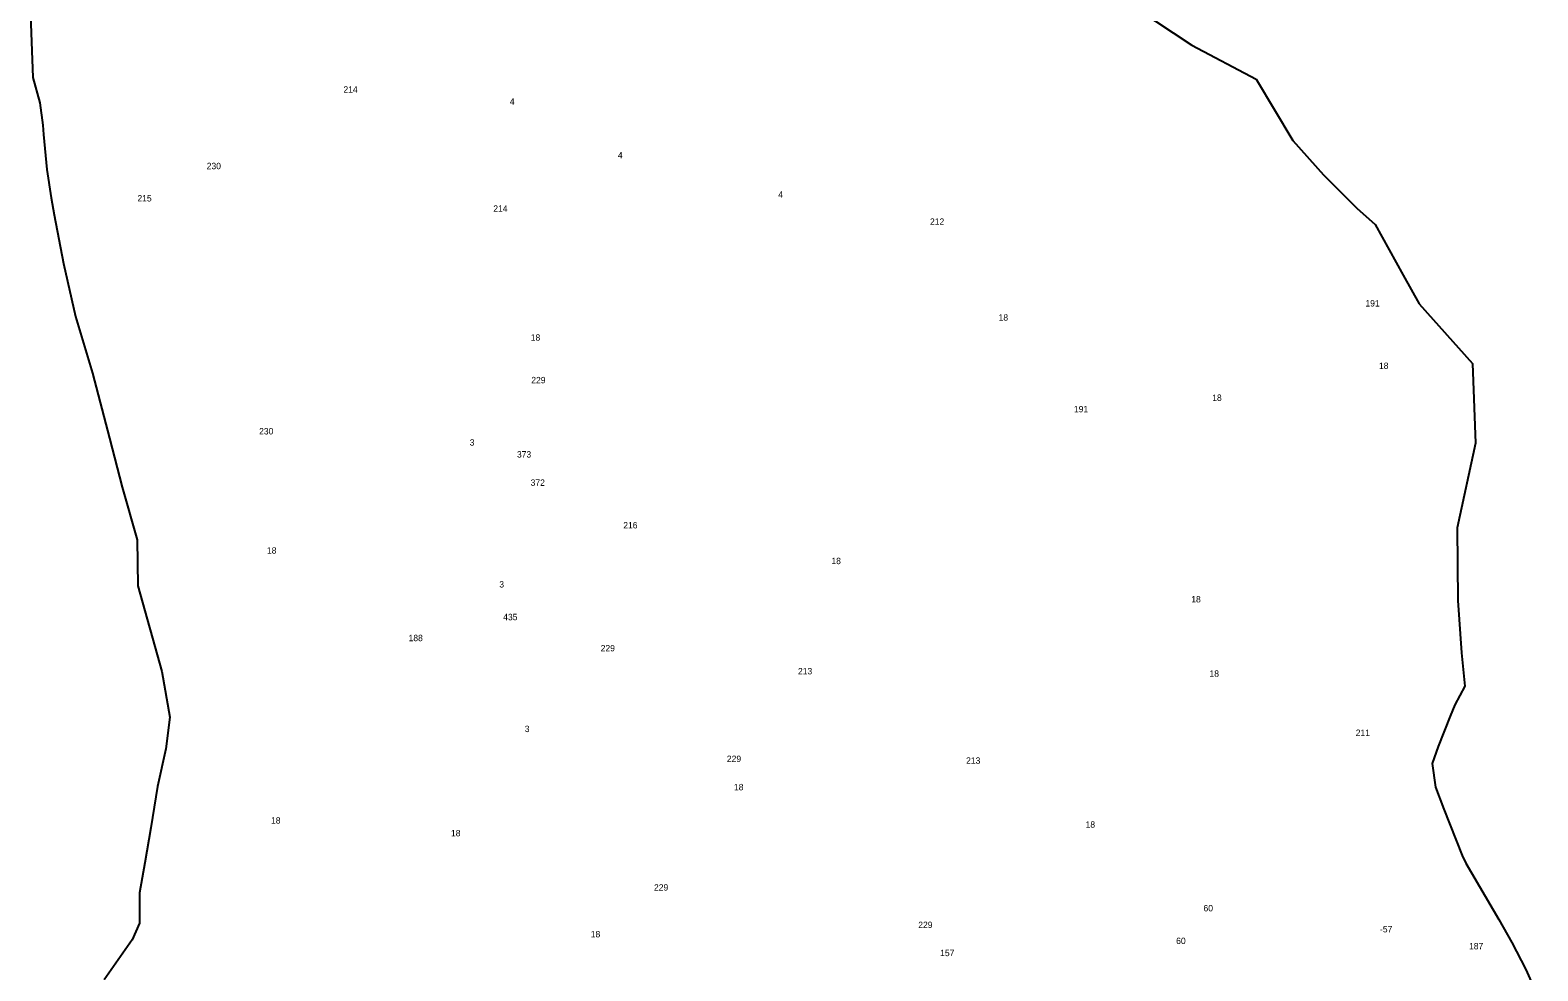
# Model space of a CAD drawing. Extents: x -784109 to -782312, y -974244 to -970866.
# Drawn here: x -784109 to -782747, y -972551 to -971701 of the extents above; entities that cross this region are included whole.
import ezdxf

# ---------------------------------------------------------------- set-up
doc = ezdxf.new("R2010")
doc.units = 0
doc.layers.add('Vrstva 13', color=7, linetype='Continuous')
doc.layers.add('Vrstva 24', color=7, linetype='Continuous')

msp = doc.modelspace()

# ---------------------------------------------------------------- linework, layer by layer
at = {"layer": 'Vrstva 13'}
for p, q in [((-784108.94, -971679.6), (-784106.6, -971743.94)), ((-783109.02, -971681.97), (-783059.31, -971714.69)), ((-783059.31, -971714.69), (-783001.1, -971745.38)), ((-784106.6, -971743.94), (-784100.18, -971766.7)), ((-783001.1, -971745.38), (-782968.1, -971800.86)), ((-784100.18, -971766.7), (-784097.5, -971786.9)), ((-784097.5, -971786.9), (-784096.81, -971795.31)), ((-784096.81, -971795.31), (-784094.01, -971827.06)), ((-782968.1, -971800.86), (-782940.26, -971831.9)), ((-784094.01, -971827.06), (-784089.81, -971852.51)), ((-782940.26, -971831.9), (-782910.24, -971862.08)), ((-784089.81, -971852.51), (-784087.24, -971868.04)), ((-782910.24, -971862.08), (-782893.59, -971876.77)), ((-784087.24, -971868.04), (-784078.84, -971911.94)), ((-782893.59, -971876.77), (-782868.37, -971922.43)), ((-784078.84, -971911.94), (-784068.07, -971959.81)), ((-782868.37, -971922.43), (-782853.98, -971948.24)), ((-782853.98, -971948.24), (-782805.79, -972002.19)), ((-784068.07, -971959.81), (-784052.69, -972010.82)), ((-784052.69, -972010.82), (-784037.23, -972069.65)), ((-782805.79, -972002.19), (-782803.02, -972074.24)), ((-784037.23, -972069.65), (-784025.79, -972114.01)), ((-782803.02, -972074.24), (-782819.67, -972150.58)), ((-784025.79, -972114.01), (-784012.26, -972161.41)), ((-784012.26, -972161.41), (-784011.59, -972202.98)), ((-782819.67, -972150.58), (-782819.09, -972216.09)), ((-784011.59, -972202.98), (-783989.83, -972280.32)), ((-782819.09, -972216.09), (-782815.75, -972263.49)), ((-782815.75, -972263.49), (-782812.71, -972293.53)), ((-783989.83, -972280.32), (-783982.66, -972321.69)), ((-782812.71, -972293.53), (-782821.58, -972310.58)), ((-782821.58, -972310.58), (-782826.05, -972320.69)), ((-783982.66, -972321.69), (-783986.26, -972350.29)), ((-782826.05, -972320.69), (-782836.83, -972348)), ((-783986.26, -972350.29), (-783993.77, -972384.26)), ((-782836.83, -972348), (-782842.07, -972363.5)), ((-782842.07, -972363.5), (-782839.14, -972384.69)), ((-783993.77, -972384.26), (-783999.84, -972421.51)), ((-782839.14, -972384.69), (-782831.58, -972404.58)), ((-782831.58, -972404.58), (-782815.01, -972446.59)), ((-783999.84, -972421.51), (-784005.29, -972453.2)), ((-782815.01, -972446.59), (-782811.66, -972453.32)), ((-784005.29, -972453.2), (-784010.19, -972480.06)), ((-782811.66, -972453.32), (-782782.06, -972504.26)), ((-784010.19, -972480.06), (-784010.19, -972507.61)), ((-784010.19, -972507.61), (-784016.84, -972522.67)), ((-782782.06, -972504.26), (-782770.15, -972525.05)), ((-784016.84, -972522.67), (-784042.05, -972558.63)), ((-782770.15, -972525.05), (-782757.42, -972549.41)), ((-782757.42, -972549.41), (-782746.7, -972573.88))]:
    msp.add_line(p, q, dxfattribs=at)

# ---------------------------------------------------------------- texts
at = {"layer": 'Vrstva 24'}
for s, p in [('214', (-783825.881, -971757.672)), ('4', (-783675.508, -971768.452)), ('230', (-783949.409, -971826.752)), ('4', (-783577.928, -971817.062)), ('4', (-783432.998, -971852.482)), ('215', (-784012.015, -971855.892)), ('214', (-783690.451, -971865.152)), ('212', (-783295.895, -971876.982)), ('18', (-783233.935, -971963.502)), ('191', (-782902.461, -971950.742)), ('18', (-783656.615, -971981.632)), ('18', (-782890.265, -972007.152)), ('229', (-783656.136, -972020.062)), ('18', (-783040.895, -972035.972)), ('191', (-783165.861, -972046.262)), ('230', (-783902.069, -972066.282)), ('3', (-783711.823, -972076.382)), ('373', (-783669.105, -972087.122)), ('372', (-783656.735, -972112.692)), ('216', (-783573.039, -972151.162)), ('18', (-783895.005, -972173.902)), ('18', (-783384.975, -972183.382)), ('3', (-783685.053, -972204.482)), ('18', (-783059.835, -972217.962)), ('435', (-783681.528, -972234.012)), ('188', (-783767.015, -972252.952)), ('229', (-783593.446, -972262.152)), ('213', (-783415.175, -972282.922)), ('18', (-783043.375, -972285.082)), ('3', (-783662.003, -972335.052)), ('211', (-782911.258, -972338.522)), ('229', (-783479.416, -972362.032)), ('213', (-783263.285, -972363.632)), ('18', (-783473.055, -972387.602)), ('18', (-783891.305, -972417.652)), ('18', (-783155.325, -972421.372)), ('18', (-783728.735, -972429.182)), ('229', (-783545.286, -972478.192)), ('60', (-783048.773, -972496.962)), ('18', (-783602.385, -972520.392)), ('229', (-783306.486, -972511.972)), ('-57', (-782889.309, -972515.94)), ('60', (-783073.473, -972526.402)), ('187', (-782808.867, -972531.242)), ('157', (-783286.727, -972537.392))]:
    msp.add_text(s, height=5.76, dxfattribs=at).set_placement(p)

doc.saveas('drawing.dxf')
